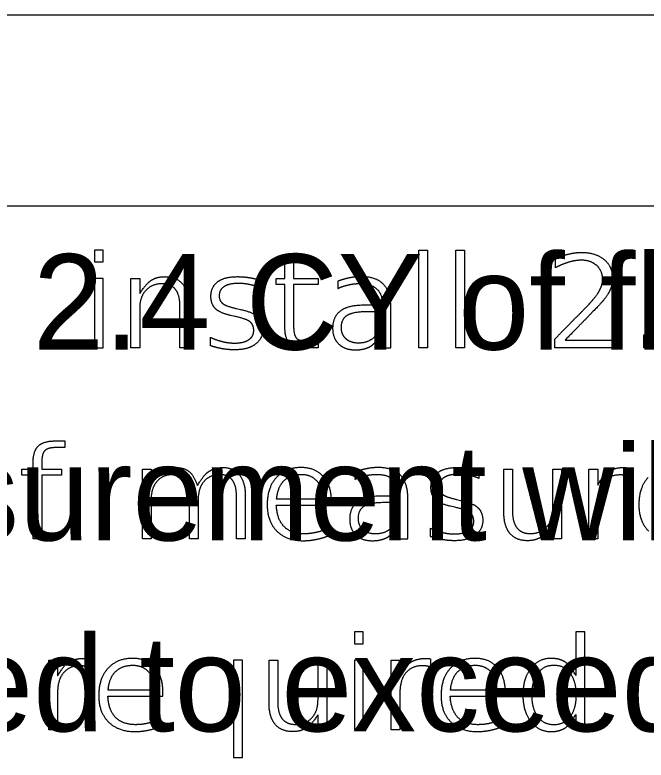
# Model space of a CAD drawing. Extents: x 0.11 to 2.72, y -0.17 to 1.89.
# Drawn here: x 1.38 to 1.4627, y 1.2854 to 1.383 of the extents above; entities that cross this region are included whole.
import ezdxf

# ---------------------------------------------------------------- set-up
doc = ezdxf.new("R2010")
doc.units = 0
doc.layers.add('SheetGridMinor', color=7, linetype='Continuous')
doc.layers.add('SheetText', color=7, linetype='Continuous')

msp = doc.modelspace()

# ---------------------------------------------------------------- linework, layer by layer
at = {"layer": 'SheetGridMinor'}
for p, q in [((0.15035, 1.383023), (1.949121, 1.383023)), ((0.15035, 1.358023), (1.949121, 1.358023))]:
    msp.add_line(p, q, dxfattribs=at)
at = {"layer": 'SheetText'}
for p, q in [((1.450839, 1.349911), (1.450839, 1.351137)), ((1.411977, 1.348294), (1.411977, 1.347306)), ((1.422346, 1.34814), (1.422346, 1.347195)), ((1.409048, 1.344556), (1.409584, 1.344437)), ((1.408818, 1.343534), (1.408273, 1.343662)), ((1.405626, 1.339686), (1.405626, 1.340801)), ((1.460384, 1.323685), (1.460393, 1.322629)), ((1.424576, 1.32314), (1.424576, 1.322195)), ((1.440813, 1.323293), (1.440813, 1.322306)), ((1.403937, 1.321369), (1.403937, 1.321369)), ((1.420338, 1.31959), (1.41431, 1.319581)), ((1.437884, 1.319556), (1.438421, 1.319437)), ((1.437655, 1.318534), (1.43711, 1.318662)), ((1.421113, 1.314814), (1.421113, 1.315793)), ((1.434462, 1.314686), (1.434462, 1.315801)), ((1.389597, 1.298685), (1.389605, 1.297629)), ((1.434462, 1.298685), (1.434471, 1.297629)), ((1.398262, 1.29459), (1.392234, 1.294581)), ((1.443128, 1.29459), (1.4371, 1.294581)), ((1.402909, 1.293943), (1.402909, 1.293943)), ((1.447774, 1.293943), (1.447774, 1.293943)), ((1.399037, 1.289813), (1.399037, 1.290793)), ((1.443902, 1.289813), (1.443902, 1.290793))]:
    msp.add_line(p, q, dxfattribs=at)
for points in [[(1.390424, 1.352218), (1.390424, 1.35066), (1.391564, 1.35066), (1.391564, 1.352218)], [(1.43293, 1.352218), (1.43407, 1.352218), (1.43407, 1.339396), (1.43293, 1.339396)], [(1.437777, 1.352218), (1.438918, 1.352218), (1.438918, 1.339396), (1.437777, 1.339396)], [(1.390424, 1.348506), (1.390424, 1.339396), (1.391564, 1.339396), (1.391564, 1.348506)], [(1.462433, 1.341133), (1.463804, 1.341133), (1.463804, 1.339396), (1.462433, 1.339396)], [(1.424524, 1.302218), (1.424524, 1.30066), (1.425664, 1.30066), (1.425664, 1.302218)], [(1.424524, 1.298506), (1.424524, 1.289396), (1.425664, 1.289396), (1.425664, 1.298506)]]:
    msp.add_lwpolyline(points, close=True, dxfattribs=at)
for points in [[(1.415378, 1.342325), (1.415378, 1.347715), (1.414229, 1.347715), (1.414229, 1.348506), (1.415378, 1.348506), (1.415378, 1.351214), (1.416528, 1.351214), (1.416528, 1.348506), (1.419754, 1.348506), (1.419754, 1.347715), (1.416528, 1.347715), (1.416528, 1.342325)], [(1.396361, 1.344573), (1.396361, 1.339396), (1.395211, 1.339396), (1.395211, 1.348506), (1.396361, 1.348506), (1.396361, 1.346523)], [(1.428135, 1.345356), (1.428135, 1.34499), (1.425726, 1.34499)], [(1.402772, 1.344939), (1.402772, 1.339396), (1.401631, 1.339396), (1.401631, 1.344888)], [(1.426364, 1.34419), (1.428135, 1.34419), (1.428135, 1.343628)], [(1.428135, 1.34138), (1.428135, 1.339396), (1.429276, 1.339396), (1.429276, 1.344624)], [(1.418358, 1.340282), (1.419754, 1.340282), (1.419754, 1.339396), (1.418358, 1.339396)], [(1.452099, 1.340418), (1.458399, 1.340418), (1.458399, 1.339396), (1.450754, 1.339396), (1.450754, 1.340546)], [(1.38527, 1.327218), (1.386538, 1.327218), (1.386538, 1.326341), (1.385253, 1.326341)], [(1.383541, 1.324562), (1.383541, 1.323506), (1.386121, 1.323506), (1.386121, 1.322715), (1.383541, 1.322715), (1.383541, 1.314396), (1.382392, 1.314396), (1.382392, 1.322715), (1.380893, 1.322715), (1.380893, 1.323506), (1.382392, 1.323506), (1.382392, 1.324383)], [(1.397857, 1.319573), (1.397857, 1.314396), (1.396708, 1.314396), (1.396708, 1.323506), (1.397857, 1.323506), (1.397857, 1.32148)], [(1.444078, 1.317947), (1.444078, 1.323506), (1.445219, 1.323506), (1.445219, 1.318006)], [(1.450498, 1.318313), (1.450498, 1.323506), (1.451639, 1.323506), (1.451639, 1.314396), (1.450498, 1.314396), (1.450498, 1.316363)], [(1.456383, 1.319207), (1.456383, 1.314396), (1.455233, 1.314396), (1.455233, 1.323506), (1.456383, 1.323506), (1.456383, 1.321429)], [(1.40403, 1.319573), (1.40403, 1.314396), (1.402881, 1.314396), (1.402881, 1.319888)], [(1.410203, 1.319939), (1.410203, 1.314396), (1.409053, 1.314396), (1.409053, 1.319888)], [(1.430366, 1.320356), (1.430366, 1.31999), (1.427956, 1.31999)], [(1.414259, 1.31879), (1.421479, 1.31879), (1.421479, 1.319343)], [(1.428595, 1.31919), (1.430366, 1.31919), (1.430366, 1.318628)], [(1.430366, 1.31638), (1.430366, 1.314396), (1.431506, 1.314396), (1.431506, 1.319624)], [(1.453538, 1.291406), (1.453538, 1.289396), (1.454679, 1.289396), (1.454679, 1.302218), (1.453538, 1.302218), (1.453538, 1.29648)], [(1.385595, 1.294207), (1.385595, 1.289396), (1.384446, 1.289396), (1.384446, 1.298506), (1.385595, 1.298506), (1.385595, 1.296429)], [(1.408673, 1.291406), (1.408673, 1.285769), (1.409814, 1.285769), (1.409814, 1.298506), (1.408673, 1.298506), (1.408673, 1.29648)], [(1.413309, 1.292947), (1.413309, 1.298506), (1.41445, 1.298506), (1.41445, 1.293006)], [(1.419729, 1.293313), (1.419729, 1.298506), (1.420869, 1.298506), (1.420869, 1.289396), (1.419729, 1.289396), (1.419729, 1.291363)], [(1.430461, 1.294207), (1.430461, 1.289396), (1.429311, 1.289396), (1.429311, 1.298506), (1.430461, 1.298506), (1.430461, 1.296429)], [(1.392183, 1.293789), (1.399403, 1.293789), (1.399403, 1.294343)], [(1.437049, 1.293789), (1.444269, 1.293789), (1.444269, 1.294343)]]:
    msp.add_lwpolyline(points, dxfattribs=at)
for points in [[(1.452614, 1.351703), (1.453495, 1.351912), (1.454219, 1.351912)], [(1.454219, 1.351912), (1.456117, 1.351912), (1.457224, 1.35098)], [(1.450839, 1.351137), (1.451733, 1.351495), (1.452614, 1.351703)], [(1.457224, 1.35098), (1.458331, 1.350047), (1.458331, 1.348498)], [(1.452486, 1.350601), (1.451562, 1.350311), (1.450839, 1.349911)], [(1.454253, 1.35089), (1.45341, 1.35089), (1.452486, 1.350601)], [(1.456254, 1.350192), (1.455479, 1.35089), (1.454253, 1.35089)], [(1.457028, 1.348387), (1.457028, 1.349494), (1.456254, 1.350192)], [(1.396361, 1.346523), (1.397289, 1.347936), (1.398004, 1.348336)], [(1.398004, 1.348336), (1.398719, 1.348736), (1.399656, 1.348736)], [(1.399656, 1.348736), (1.401197, 1.348736), (1.401984, 1.347787)], [(1.405694, 1.346139), (1.405694, 1.347383), (1.406575, 1.348059)], [(1.406575, 1.348059), (1.407456, 1.348736), (1.409142, 1.348736)], [(1.409142, 1.348736), (1.409993, 1.348736), (1.410738, 1.348613)], [(1.410738, 1.348613), (1.411483, 1.348489), (1.411977, 1.348294)], [(1.423844, 1.348574), (1.423052, 1.348413), (1.422346, 1.34814)], [(1.425377, 1.348736), (1.424636, 1.348736), (1.423844, 1.348574)], [(1.428314, 1.347727), (1.427352, 1.348736), (1.425377, 1.348736)], [(1.456683, 1.347038), (1.457028, 1.347715), (1.457028, 1.348387)], [(1.458331, 1.348498), (1.458331, 1.347757), (1.45805, 1.347089)], [(1.399306, 1.3478), (1.397944, 1.3478), (1.397152, 1.346927)], [(1.401048, 1.347059), (1.400464, 1.3478), (1.399306, 1.3478)], [(1.401631, 1.344888), (1.401631, 1.346318), (1.401048, 1.347059)], [(1.401984, 1.347787), (1.402772, 1.346838), (1.402772, 1.344939)], [(1.407443, 1.347446), (1.406783, 1.347042), (1.406783, 1.346208)], [(1.409329, 1.347851), (1.408103, 1.347851), (1.407443, 1.347446)], [(1.410862, 1.347676), (1.410121, 1.347851), (1.409329, 1.347851)], [(1.411977, 1.347306), (1.411602, 1.347502), (1.410862, 1.347676)], [(1.422346, 1.347195), (1.422771, 1.347425), (1.423572, 1.347629)], [(1.423572, 1.347629), (1.424372, 1.347834), (1.425215, 1.347834)], [(1.425215, 1.347834), (1.426577, 1.347834), (1.427356, 1.347187)], [(1.427356, 1.347187), (1.428135, 1.34654), (1.428135, 1.345356)], [(1.429276, 1.344624), (1.429276, 1.346718), (1.428314, 1.347727)], [(1.455496, 1.345407), (1.456339, 1.346361), (1.456683, 1.347038)], [(1.45805, 1.347089), (1.457769, 1.34642), (1.45702, 1.345492)], [(1.397152, 1.346927), (1.396361, 1.346054), (1.396361, 1.344573)], [(1.406285, 1.344543), (1.405694, 1.345126), (1.405694, 1.346139)], [(1.406783, 1.346208), (1.406783, 1.345552), (1.40726, 1.345199)], [(1.40726, 1.345199), (1.407737, 1.344845), (1.409048, 1.344556)], [(1.453363, 1.343206), (1.455053, 1.344913), (1.455496, 1.345407)], [(1.45702, 1.345492), (1.456815, 1.345254), (1.455675, 1.344075)], [(1.408273, 1.343662), (1.406877, 1.34396), (1.406285, 1.344543)], [(1.409584, 1.344437), (1.411194, 1.344088), (1.411841, 1.343487)], [(1.422652, 1.344228), (1.421648, 1.343466), (1.421648, 1.341959)], [(1.425726, 1.34499), (1.423657, 1.34499), (1.422652, 1.344228)], [(1.423597, 1.343709), (1.424406, 1.34419), (1.426364, 1.34419)], [(1.410815, 1.342823), (1.410325, 1.343211), (1.408818, 1.343534)], [(1.411841, 1.343487), (1.412488, 1.342887), (1.412488, 1.341814)], [(1.422788, 1.342061), (1.422788, 1.343228), (1.423597, 1.343709)], [(1.428135, 1.343628), (1.428135, 1.342019), (1.427292, 1.341027)], [(1.450754, 1.340546), (1.451673, 1.341499), (1.453363, 1.343206)], [(1.455675, 1.344075), (1.454534, 1.342896), (1.452099, 1.340418)], [(1.411304, 1.341695), (1.411304, 1.342436), (1.410815, 1.342823)], [(1.416004, 1.340009), (1.415378, 1.340622), (1.415378, 1.342325)], [(1.416528, 1.342325), (1.416528, 1.341074), (1.416906, 1.340678)], [(1.410632, 1.340461), (1.411304, 1.340886), (1.411304, 1.341695)], [(1.412488, 1.341814), (1.412488, 1.340597), (1.411509, 1.339873)], [(1.421648, 1.341959), (1.421648, 1.340674), (1.422448, 1.339912)], [(1.423402, 1.340584), (1.422788, 1.341133), (1.422788, 1.342061)], [(1.426484, 1.339537), (1.427233, 1.339924), (1.428135, 1.34138)], [(1.405626, 1.340801), (1.406205, 1.340503), (1.407073, 1.340269)], [(1.407073, 1.340269), (1.407941, 1.340035), (1.408793, 1.340035)], [(1.408793, 1.340035), (1.409959, 1.340035), (1.410632, 1.340461)], [(1.416906, 1.340678), (1.417285, 1.340282), (1.418358, 1.340282)], [(1.425045, 1.340035), (1.424015, 1.340035), (1.423402, 1.340584)], [(1.427292, 1.341027), (1.42645, 1.340035), (1.425045, 1.340035)], [(1.407196, 1.339294), (1.406383, 1.339439), (1.405626, 1.339686)], [(1.408759, 1.339149), (1.408009, 1.339149), (1.407196, 1.339294)], [(1.411509, 1.339873), (1.41053, 1.339149), (1.408759, 1.339149)], [(1.418358, 1.339396), (1.41663, 1.339396), (1.416004, 1.340009)], [(1.422448, 1.339912), (1.423248, 1.339149), (1.424627, 1.339149)], [(1.424627, 1.339149), (1.425734, 1.339149), (1.426484, 1.339537)], [(1.382392, 1.324383), (1.382392, 1.32589), (1.383069, 1.326554)], [(1.383069, 1.326554), (1.383746, 1.327218), (1.38527, 1.327218)], [(1.383929, 1.325937), (1.383541, 1.325533), (1.383541, 1.324562)], [(1.385253, 1.326341), (1.384316, 1.326341), (1.383929, 1.325937)], [(1.399458, 1.323345), (1.400156, 1.323736), (1.401135, 1.323736)], [(1.401135, 1.323736), (1.402106, 1.323736), (1.402779, 1.323247)], [(1.405495, 1.323264), (1.406261, 1.323736), (1.407308, 1.323736)], [(1.407308, 1.323736), (1.408696, 1.323736), (1.409449, 1.322761)], [(1.417529, 1.323736), (1.415477, 1.323736), (1.414272, 1.322425)], [(1.420419, 1.322561), (1.419359, 1.323736), (1.417529, 1.323736)], [(1.427607, 1.323736), (1.426866, 1.323736), (1.426075, 1.323574)], [(1.430544, 1.322727), (1.429582, 1.323736), (1.427607, 1.323736)], [(1.435411, 1.323059), (1.436292, 1.323736), (1.437978, 1.323736)], [(1.437978, 1.323736), (1.43883, 1.323736), (1.439574, 1.323613)], [(1.439574, 1.323613), (1.440319, 1.323489), (1.440813, 1.323293)], [(1.457983, 1.32334), (1.458724, 1.323736), (1.459805, 1.323736)], [(1.459805, 1.323736), (1.459959, 1.323736), (1.460142, 1.323715)], [(1.460142, 1.323715), (1.460325, 1.323694), (1.460384, 1.323685)], [(1.397857, 1.32148), (1.39876, 1.322953), (1.399458, 1.323345)], [(1.400684, 1.3228), (1.39939, 1.3228), (1.398624, 1.321918)], [(1.402344, 1.322067), (1.401808, 1.3228), (1.400684, 1.3228)], [(1.402779, 1.323247), (1.403451, 1.322757), (1.403937, 1.321369)], [(1.403937, 1.321369), (1.404728, 1.322791), (1.405495, 1.323264)], [(1.406874, 1.3228), (1.405563, 1.3228), (1.404796, 1.321923)], [(1.408517, 1.322063), (1.407981, 1.3228), (1.406874, 1.3228)], [(1.409449, 1.322761), (1.410203, 1.321786), (1.410203, 1.319939)], [(1.415302, 1.322038), (1.416149, 1.322834), (1.417546, 1.322834)], [(1.417546, 1.322834), (1.418797, 1.322834), (1.419559, 1.322004)], [(1.426075, 1.323574), (1.425283, 1.323413), (1.424576, 1.32314)], [(1.424576, 1.322195), (1.425002, 1.322425), (1.425802, 1.322629)], [(1.425802, 1.322629), (1.426602, 1.322834), (1.427445, 1.322834)], [(1.427445, 1.322834), (1.428808, 1.322834), (1.429587, 1.322187)], [(1.431506, 1.319624), (1.431506, 1.321718), (1.430544, 1.322727)], [(1.43453, 1.321139), (1.43453, 1.322382), (1.435411, 1.323059)], [(1.438165, 1.322851), (1.436939, 1.322851), (1.43628, 1.322446)], [(1.439698, 1.322676), (1.438957, 1.322851), (1.438165, 1.322851)], [(1.440813, 1.322306), (1.440439, 1.322502), (1.439698, 1.322676)], [(1.456383, 1.321429), (1.457243, 1.322944), (1.457983, 1.32334)], [(1.459345, 1.322766), (1.457915, 1.322766), (1.457149, 1.321833)], [(1.460086, 1.322689), (1.459746, 1.322766), (1.459345, 1.322766)], [(1.460384, 1.322621), (1.460342, 1.322621), (1.460086, 1.322689)], [(1.460393, 1.322629), (1.460393, 1.322621), (1.460384, 1.322621)], [(1.398624, 1.321918), (1.397857, 1.321037), (1.397857, 1.319573)], [(1.402881, 1.319888), (1.402881, 1.321335), (1.402344, 1.322067)], [(1.404796, 1.321923), (1.40403, 1.321046), (1.40403, 1.319573)], [(1.409053, 1.319888), (1.409053, 1.321327), (1.408517, 1.322063)], [(1.414272, 1.322425), (1.413067, 1.321114), (1.413067, 1.318858)], [(1.41431, 1.319581), (1.414455, 1.321242), (1.415302, 1.322038)], [(1.419559, 1.322004), (1.420321, 1.321173), (1.420338, 1.31959)], [(1.421479, 1.319343), (1.421479, 1.321386), (1.420419, 1.322561)], [(1.429587, 1.322187), (1.430366, 1.32154), (1.430366, 1.320356)], [(1.43628, 1.322446), (1.43562, 1.322042), (1.43562, 1.321207)], [(1.457149, 1.321833), (1.456383, 1.320901), (1.456383, 1.319207)], [(1.462983, 1.322425), (1.461779, 1.321114), (1.461779, 1.318858)], [(1.435122, 1.319543), (1.43453, 1.320126), (1.43453, 1.321139)], [(1.43562, 1.321207), (1.43562, 1.320552), (1.436097, 1.320199)], [(1.427956, 1.31999), (1.425887, 1.31999), (1.424883, 1.319228)], [(1.436097, 1.320199), (1.436573, 1.319845), (1.437884, 1.319556)], [(1.413067, 1.318858), (1.413067, 1.316678), (1.414336, 1.315414)], [(1.415319, 1.315959), (1.414387, 1.316865), (1.414259, 1.31879)], [(1.424883, 1.319228), (1.423878, 1.318466), (1.423878, 1.316959)], [(1.425019, 1.317061), (1.425019, 1.318228), (1.425828, 1.318709)], [(1.425828, 1.318709), (1.426636, 1.31919), (1.428595, 1.31919)], [(1.43711, 1.318662), (1.435713, 1.31896), (1.435122, 1.319543)], [(1.438421, 1.319437), (1.44003, 1.319088), (1.440677, 1.318487)], [(1.461779, 1.318858), (1.461779, 1.316678), (1.463047, 1.315414)], [(1.430366, 1.318628), (1.430366, 1.317019), (1.429523, 1.316027)], [(1.439651, 1.317823), (1.439162, 1.318211), (1.437655, 1.318534)], [(1.440141, 1.316695), (1.440141, 1.317436), (1.439651, 1.317823)], [(1.440677, 1.318487), (1.441324, 1.317887), (1.441324, 1.316814)], [(1.444874, 1.315103), (1.444078, 1.316057), (1.444078, 1.317947)], [(1.445219, 1.318006), (1.445219, 1.316576), (1.445802, 1.315831)], [(1.449702, 1.315959), (1.450498, 1.316831), (1.450498, 1.318313)], [(1.423878, 1.316959), (1.423878, 1.315673), (1.424678, 1.314911)], [(1.425632, 1.315584), (1.425019, 1.316133), (1.425019, 1.317061)], [(1.441324, 1.316814), (1.441324, 1.315597), (1.440345, 1.314873)], [(1.417895, 1.315052), (1.416251, 1.315052), (1.415319, 1.315959)], [(1.421113, 1.315793), (1.420568, 1.315512), (1.419695, 1.315282)], [(1.429523, 1.316027), (1.42868, 1.315035), (1.427275, 1.315035)], [(1.428714, 1.314537), (1.429463, 1.314924), (1.430366, 1.31638)], [(1.434462, 1.315801), (1.435041, 1.315503), (1.435909, 1.315269)], [(1.439468, 1.315461), (1.440141, 1.315886), (1.440141, 1.316695)], [(1.445802, 1.315831), (1.446386, 1.315086), (1.447544, 1.315086)], [(1.447544, 1.315086), (1.448906, 1.315086), (1.449702, 1.315959)], [(1.450498, 1.316363), (1.449561, 1.314941), (1.448855, 1.314545)], [(1.414336, 1.315414), (1.415604, 1.314149), (1.417801, 1.314149)], [(1.419695, 1.315282), (1.418823, 1.315052), (1.417895, 1.315052)], [(1.419551, 1.314332), (1.420415, 1.314516), (1.421113, 1.314814)], [(1.424678, 1.314911), (1.425479, 1.314149), (1.426858, 1.314149)], [(1.427275, 1.315035), (1.426245, 1.315035), (1.425632, 1.315584)], [(1.435909, 1.315269), (1.436778, 1.315035), (1.437629, 1.315035)], [(1.440345, 1.314873), (1.439366, 1.314149), (1.437595, 1.314149)], [(1.437629, 1.315035), (1.438795, 1.315035), (1.439468, 1.315461)], [(1.447211, 1.314149), (1.44567, 1.314149), (1.444874, 1.315103)], [(1.417801, 1.314149), (1.418686, 1.314149), (1.419551, 1.314332)], [(1.426858, 1.314149), (1.427965, 1.314149), (1.428714, 1.314537)], [(1.436033, 1.314294), (1.43522, 1.314439), (1.434462, 1.314686)], [(1.437595, 1.314149), (1.436846, 1.314149), (1.436033, 1.314294)], [(1.448855, 1.314545), (1.448148, 1.314149), (1.447211, 1.314149)], [(1.385595, 1.296429), (1.386455, 1.297944), (1.387196, 1.29834)], [(1.387196, 1.29834), (1.387937, 1.298736), (1.389018, 1.298736)], [(1.389018, 1.298736), (1.389171, 1.298736), (1.389354, 1.298715)], [(1.389354, 1.298715), (1.389537, 1.298694), (1.389597, 1.298685)], [(1.395453, 1.298736), (1.393401, 1.298736), (1.392196, 1.297425)], [(1.398343, 1.297561), (1.397283, 1.298736), (1.395453, 1.298736)], [(1.405404, 1.298736), (1.403777, 1.298736), (1.402747, 1.297425)], [(1.407111, 1.298349), (1.406408, 1.298736), (1.405404, 1.298736)], [(1.408673, 1.29648), (1.407813, 1.297961), (1.407111, 1.298349)], [(1.430461, 1.296429), (1.431321, 1.297944), (1.432061, 1.29834)], [(1.432061, 1.29834), (1.432802, 1.298736), (1.433883, 1.298736)], [(1.433883, 1.298736), (1.434037, 1.298736), (1.43422, 1.298715)], [(1.43422, 1.298715), (1.434403, 1.298694), (1.434462, 1.298685)], [(1.440318, 1.298736), (1.438266, 1.298736), (1.437062, 1.297425)], [(1.443209, 1.297561), (1.442149, 1.298736), (1.440318, 1.298736)], [(1.450269, 1.298736), (1.448643, 1.298736), (1.447613, 1.297425)], [(1.451976, 1.298349), (1.451274, 1.298736), (1.450269, 1.298736)], [(1.453538, 1.29648), (1.452678, 1.297961), (1.451976, 1.298349)], [(1.388558, 1.297766), (1.387128, 1.297766), (1.386362, 1.296833)], [(1.389299, 1.297689), (1.388958, 1.297766), (1.388558, 1.297766)], [(1.389597, 1.297621), (1.389554, 1.297621), (1.389299, 1.297689)], [(1.389605, 1.297629), (1.389605, 1.297621), (1.389597, 1.297621)], [(1.392196, 1.297425), (1.390991, 1.296114), (1.390991, 1.293858)], [(1.393226, 1.297038), (1.394073, 1.297834), (1.39547, 1.297834)], [(1.39547, 1.297834), (1.396721, 1.297834), (1.397483, 1.297003)], [(1.399403, 1.294343), (1.399403, 1.296386), (1.398343, 1.297561)], [(1.402747, 1.297425), (1.401717, 1.296114), (1.401717, 1.293943)], [(1.403671, 1.296795), (1.404433, 1.297851), (1.405787, 1.297851)], [(1.405787, 1.297851), (1.407141, 1.297851), (1.407907, 1.296795)], [(1.433424, 1.297766), (1.431993, 1.297766), (1.431227, 1.296833)], [(1.434164, 1.297689), (1.433824, 1.297766), (1.433424, 1.297766)], [(1.434462, 1.297621), (1.43442, 1.297621), (1.434164, 1.297689)], [(1.434471, 1.297629), (1.434471, 1.297621), (1.434462, 1.297621)], [(1.437062, 1.297425), (1.435857, 1.296114), (1.435857, 1.293858)], [(1.438092, 1.297038), (1.438939, 1.297834), (1.440335, 1.297834)], [(1.440335, 1.297834), (1.441587, 1.297834), (1.442349, 1.297003)], [(1.444269, 1.294343), (1.444269, 1.296386), (1.443209, 1.297561)], [(1.447613, 1.297425), (1.446582, 1.296114), (1.446582, 1.293943)], [(1.448536, 1.296795), (1.449298, 1.297851), (1.450652, 1.297851)], [(1.450652, 1.297851), (1.452006, 1.297851), (1.452772, 1.296795)], [(1.386362, 1.296833), (1.385595, 1.295901), (1.385595, 1.294207)], [(1.392234, 1.294581), (1.392379, 1.296241), (1.393226, 1.297038)], [(1.397483, 1.297003), (1.398245, 1.296173), (1.398262, 1.29459)], [(1.402909, 1.293943), (1.402909, 1.295739), (1.403671, 1.296795)], [(1.407907, 1.296795), (1.408673, 1.295739), (1.408673, 1.293943)], [(1.431227, 1.296833), (1.430461, 1.295901), (1.430461, 1.294207)], [(1.4371, 1.294581), (1.437245, 1.296241), (1.438092, 1.297038)], [(1.442349, 1.297003), (1.443111, 1.296173), (1.443128, 1.29459)], [(1.447774, 1.293943), (1.447774, 1.295739), (1.448536, 1.296795)], [(1.452772, 1.296795), (1.453538, 1.295739), (1.453538, 1.293943)], [(1.390991, 1.293858), (1.390991, 1.291678), (1.39226, 1.290414)], [(1.393243, 1.290959), (1.392311, 1.291865), (1.392183, 1.293789)], [(1.401717, 1.293943), (1.401717, 1.291772), (1.402747, 1.290461)], [(1.403671, 1.291091), (1.402909, 1.292146), (1.402909, 1.293943)], [(1.408673, 1.293943), (1.408673, 1.292146), (1.407907, 1.291091)], [(1.435857, 1.293858), (1.435857, 1.291678), (1.437125, 1.290414)], [(1.438109, 1.290959), (1.437176, 1.291865), (1.437049, 1.293789)], [(1.446582, 1.293943), (1.446582, 1.291772), (1.447613, 1.290461)], [(1.448536, 1.291091), (1.447774, 1.292146), (1.447774, 1.293943)], [(1.453538, 1.293943), (1.453538, 1.292146), (1.452772, 1.291091)], [(1.414105, 1.290103), (1.413309, 1.291056), (1.413309, 1.292947)], [(1.41445, 1.293006), (1.41445, 1.291576), (1.415033, 1.290831)], [(1.418932, 1.290959), (1.419729, 1.291831), (1.419729, 1.293313)], [(1.407111, 1.289537), (1.407813, 1.289924), (1.408673, 1.291406)], [(1.451976, 1.289537), (1.452678, 1.289924), (1.453538, 1.291406)], [(1.39226, 1.290414), (1.393529, 1.289149), (1.395725, 1.289149)], [(1.395819, 1.290052), (1.394176, 1.290052), (1.393243, 1.290959)], [(1.399037, 1.290793), (1.398492, 1.290512), (1.39762, 1.290282)], [(1.402747, 1.290461), (1.403777, 1.289149), (1.405404, 1.289149)], [(1.405787, 1.290035), (1.404433, 1.290035), (1.403671, 1.291091)], [(1.407907, 1.291091), (1.407141, 1.290035), (1.405787, 1.290035)], [(1.415033, 1.290831), (1.415616, 1.290086), (1.416774, 1.290086)], [(1.416774, 1.290086), (1.418136, 1.290086), (1.418932, 1.290959)], [(1.419729, 1.291363), (1.418792, 1.289941), (1.418085, 1.289545)], [(1.437125, 1.290414), (1.438394, 1.289149), (1.44059, 1.289149)], [(1.440684, 1.290052), (1.439041, 1.290052), (1.438109, 1.290959)], [(1.443902, 1.290793), (1.443358, 1.290512), (1.442485, 1.290282)], [(1.447613, 1.290461), (1.448643, 1.289149), (1.450269, 1.289149)], [(1.450652, 1.290035), (1.449298, 1.290035), (1.448536, 1.291091)], [(1.452772, 1.291091), (1.452006, 1.290035), (1.450652, 1.290035)], [(1.39762, 1.290282), (1.396747, 1.290052), (1.395819, 1.290052)], [(1.397475, 1.289332), (1.398339, 1.289515), (1.399037, 1.289813)], [(1.405404, 1.289149), (1.406408, 1.289149), (1.407111, 1.289537)], [(1.416442, 1.289149), (1.414901, 1.289149), (1.414105, 1.290103)], [(1.418085, 1.289545), (1.417379, 1.289149), (1.416442, 1.289149)], [(1.442485, 1.290282), (1.441612, 1.290052), (1.440684, 1.290052)], [(1.44234, 1.289332), (1.443204, 1.289515), (1.443902, 1.289813)], [(1.450269, 1.289149), (1.451274, 1.289149), (1.451976, 1.289537)], [(1.395725, 1.289149), (1.396611, 1.289149), (1.397475, 1.289332)], [(1.44059, 1.289149), (1.441476, 1.289149), (1.44234, 1.289332)]]:
    msp.add_open_spline(points, degree=2, dxfattribs=at)

# ---------------------------------------------------------------- texts
for s, p in [('Includes cost to furnish and install 2.4 CY of flowable mortar at west end of south ', (1.126865, 1.339184)), ('abutment footing. Method of measurement will be quantity placed installed. Prior ', (1.126865, 1.314183)), ('approval of the Engineer is required to exceeding 2.4 CY.  The type of product to be', (1.126865, 1.289183))]:
    msp.add_text(s, height=0.01250003, dxfattribs=at).set_placement(p)

doc.saveas('drawing.dxf')
